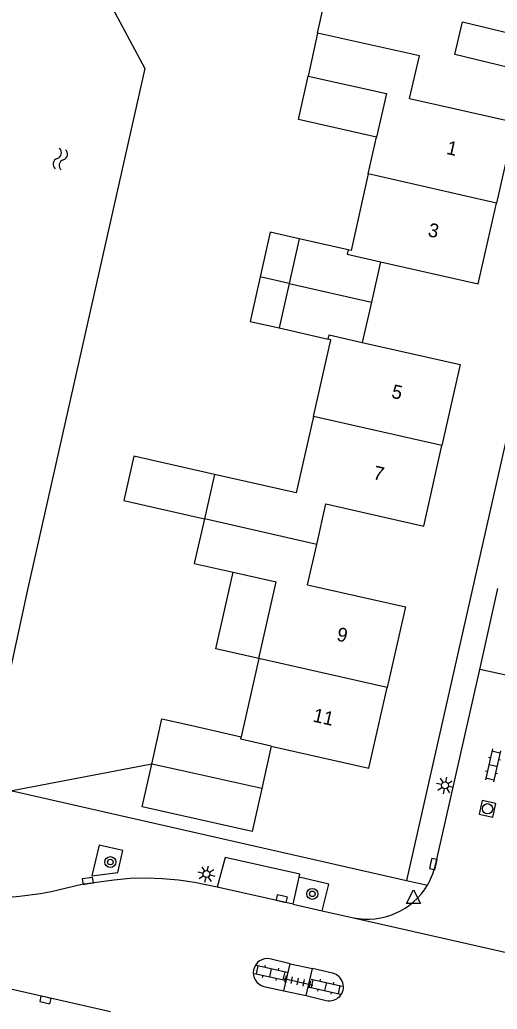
# Model space of a CAD drawing. Extents: x 128000 to 131008, y 398996 to 402500.
# Drawn here: x 128852.8 to 128887.5, y 399302.4 to 399374.1 of the extents above; entities that cross this region are included whole.
import ezdxf

# ---------------------------------------------------------------- set-up
doc = ezdxf.new("R2010")
doc.units = 0
for name, color, linetype in [('gg-afsc-erfafscheiding', 7, 'Continuous'), ('gg-anno-huisnummerreeks BGT', 7, 'Continuous'), ('gg-bbg-bijgebouw', 7, 'Continuous'), ('gg-bbg-gedigitaliseerde bebouwing', 7, 'Continuous'), ('gg-bbg-gedigitaliseerde bijgebouw', 7, 'Continuous'), ('gg-bbg-hoofdgebouw', 7, 'Continuous'), ('gg-bbg-luifel en loopbrug', 7, 'Continuous'), ('gg-bbg-tussenscheiding', 7, 'Continuous'), ('gg-knt-verharding', 7, 'Continuous'), ('gg-knt-verharding nz', 7, 'Continuous'), ('gg-kntw-beschoeiing', 7, 'Continuous'), ('gt-grn-vlakafsluiter', 7, 'Continuous'), ('gt-grn-weggrens', 7, 'Continuous'), ('gt-symb-boom', 7, 'Continuous'), ('gt-symb-klinker verharding', 7, 'Continuous'), ('gt-symb-kolk', 7, 'Continuous'), ('gt-symb-lichtmast', 7, 'Continuous'), ('gt-symb-rioolschacht', 7, 'Continuous'), ('gt-symb-tegel verharding', 7, 'Continuous'), ('gt-symb-waterafsluiter', 7, 'Continuous'), ('gt-symb-watersymbool', 7, 'Continuous')]:
    doc.layers.add(name, color=color, linetype=linetype)

# ---------------------------------------------------------------- blocks, each defined once
blk = doc.blocks.new('gt0-WA')
at = {"layer": 'gt-symb-watersymbool'}
for centre, start, end in [((-0.323, 0.022), 28.07249, 151.92751), ((0.427, 0.422), 208.07248, 331.92751), ((-0.323, -0.428), 28.07249, 151.92751), ((0.427, -0.028), 208.07248, 331.92751)]:
    blk.add_arc(centre, 0.425, start, end, dxfattribs=at)
blk = doc.blocks.new('gt0-WAFSL')
at = {"layer": 'gt-symb-waterafsluiter'}
for p, q in [((-0.5, -0.333), (0, 0.667)), ((0, 0.667), (0.5, -0.333)), ((0.5, -0.333), (-0.5, -0.333))]:
    blk.add_line(p, q, dxfattribs=at)
blk = doc.blocks.new('gt0-KOLK')
at = {"layer": 'gt-symb-kolk'}
blk.add_lwpolyline([(0, 0), (0.375, 0), (0.375, 0.4), (-0.375, 0.4), (-0.375, 0), (0, 0)], dxfattribs=at)
blk = doc.blocks.new('gt0-LMAST')
at = {"layer": 'gt-symb-lichtmast'}
for p, q in [((-0.182, 0.173), (-0.447, 0.438)), ((-0.005, 0.246), (-0.005, 0.621)), ((0.172, 0.173), (0.437, 0.438)), ((-0.255, -0.004), (-0.63, -0.004)), ((-0.182, -0.181), (-0.447, -0.446)), ((-0.005, -0.254), (-0.005, -0.629)), ((0.437, -0.446), (0.172, -0.181)), ((0.245, -0.004), (0.62, -0.004))]:
    blk.add_line(p, q, dxfattribs=at)
blk.add_circle((-0.005, -0.004), 0.25, dxfattribs=at)
blk = doc.blocks.new('gt0-RS')
at = {"layer": 'gt-symb-rioolschacht'}
blk.add_lwpolyline([(-0.5, -0.5), (0.5, -0.5), (0.5, 0.5), (-0.5, 0.5)], close=True, dxfattribs=at)
blk.add_circle((0, 0), 0.375, dxfattribs=at)
blk = doc.blocks.new('gt0-KL1')
at = {"layer": 'gt-symb-klinker verharding'}
for p, q in [((-1.15, 0.3), (1.15, 0.3)), ((-1, -0.3), (-1, 0.3)), ((-0.5, 0.3), (-0.5, 0.45)), ((0, -0.3), (0, 0.3)), ((0.5, 0.3), (0.5, 0.45)), ((1, -0.3), (1, 0.3)), ((-1.15, -0.3), (1.15, -0.3)), ((-0.5, -0.45), (-0.5, -0.3)), ((0.5, -0.45), (0.5, -0.3))]:
    blk.add_line(p, q, dxfattribs=at)
blk = doc.blocks.new('gt0-TEG1')
at = {"layer": 'gt-symb-tegel verharding'}
for p, q in [((-1.125, 0), (1.125, 0)), ((-0.9, -0.25), (-0.9, 0.25)), ((-0.45, -0.25), (-0.45, 0.25)), ((0, -0.25), (0, 0.25)), ((0.45, -0.25), (0.45, 0.25)), ((0.9, -0.25), (0.9, 0.25))]:
    blk.add_line(p, q, dxfattribs=at)
blk = doc.blocks.new('gt0-BOOM')
at = {"layer": 'gt-symb-boom'}
for radius in [0.4, 0.2]:
    blk.add_circle((0, 0), radius, dxfattribs=at)

msp = doc.modelspace()

# ---------------------------------------------------------------- linework, layer by layer
at = {"layer": 'gg-afsc-erfafscheiding'}
msp.add_line((128852.286, 399318.268), (128880.893, 399311.77), dxfattribs=at)
at = {"layer": 'gg-bbg-bijgebouw'}
msp.add_line((128871.087, 399321.504), (128870.397, 399318.43), dxfattribs=at)
for points in [[(128890.471, 399372.678), (128889.905, 399370.311), (128884.406, 399371.629), (128884.972, 399373.996), (128890.471, 399372.678)], [(128862.42, 399320.21), (128863.14, 399323.48), (128865.24, 399323.02), (128868.915, 399322.189)], [(128870.397, 399318.43), (128864.52, 399319.75), (128862.42, 399320.21)]]:
    msp.add_lwpolyline(points, dxfattribs=at)
at = {"layer": 'gg-bbg-gedigitaliseerde bebouwing'}
for p, q in [((128874.449, 399373.171), (128873.764, 399370.065)), ((128873.764, 399370.065), (128879.45, 399368.812)), ((128879.45, 399368.812), (128878.731, 399365.631)), ((128866.967, 399341.203), (128866.236, 399337.974)), ((128872.907, 399339.86), (128866.967, 399341.203)), ((128868.33, 399334.108), (128871.451, 399333.402))]:
    msp.add_line(p, q, dxfattribs=at)
msp.add_lwpolyline([(128866.236, 399337.974), (128865.506, 399334.747), (128868.33, 399334.108)], dxfattribs=at)
at = {"layer": 'gg-bbg-gedigitaliseerde bijgebouw'}
for p, q in [((128873.111, 399358.269), (128872.38, 399355.04)), ((128872.38, 399355.04), (128871.65, 399351.812))]:
    msp.add_line(p, q, dxfattribs=at)
for points in [[(128873.111, 399358.269), (128871.014, 399358.743), (128870.283, 399355.515)], [(128870.283, 399355.515), (128869.553, 399352.287), (128871.65, 399351.812)]]:
    msp.add_lwpolyline(points, dxfattribs=at)
at = {"layer": 'gg-bbg-hoofdgebouw'}
for p, q in [((128878.13, 399362.971), (128878.731, 399365.631)), ((128878.13, 399362.971), (128876.875, 399357.417)), ((128876.875, 399357.417), (128876.671, 399357.463)), ((128874.16, 399345.404), (128872.907, 399339.86)), ((128874.392, 399336.129), (128875.058, 399339.055)), ((128873.726, 399333.204), (128874.392, 399336.129)), ((128870.195, 399327.851), (128871.451, 399333.402)), ((128870.195, 399327.851), (128868.915, 399322.189))]:
    msp.add_line(p, q, dxfattribs=at)
for points in [[(128881.123, 399368.443), (128881.839, 399371.542), (128874.449, 399373.171)], [(128881.123, 399368.443), (128888.76, 399366.72), (128887.435, 399360.865)], [(128879.018, 399356.615), (128886.11, 399355.01), (128887.435, 399360.865)], [(128876.671, 399357.463), (128876.603, 399357.161), (128879.018, 399356.615)], [(128875.211, 399351.006), (128875.28, 399351.309), (128877.694, 399350.764)], [(128874.16, 399345.404), (128875.415, 399350.96), (128875.211, 399351.006)], [(128877.694, 399350.764), (128884.79, 399349.16), (128883.47, 399343.305)], [(128875.058, 399339.055), (128882.15, 399337.45), (128883.47, 399343.305)], [(128873.726, 399333.204), (128880.82, 399331.6), (128879.5, 399325.75)], [(128871.087, 399321.504), (128878.18, 399319.9), (128879.5, 399325.75)]]:
    msp.add_lwpolyline(points, dxfattribs=at)
at = {"layer": 'gg-bbg-luifel en loopbrug'}
for p, q in [((128876.671, 399357.463), (128873.111, 399358.269)), ((128879.018, 399356.615), (128878.356, 399353.689)), ((128872.38, 399355.04), (128878.356, 399353.689)), ((128878.356, 399353.689), (128877.694, 399350.764)), ((128871.65, 399351.812), (128875.211, 399351.006))]:
    msp.add_line(p, q, dxfattribs=at)
for points in [[(128878.731, 399365.631), (128873.053, 399366.914), (128873.764, 399370.065)], [(128866.967, 399341.203), (128861.115, 399342.526), (128860.385, 399339.297), (128866.236, 399337.974)], [(128870.195, 399327.851), (128867.074, 399328.557), (128868.33, 399334.108)], [(128870.397, 399318.43), (128869.691, 399315.309), (128861.719, 399317.111), (128862.42, 399320.21)]]:
    msp.add_lwpolyline(points, dxfattribs=at)
at = {"layer": 'gg-bbg-tussenscheiding'}
for p, q in [((128887.435, 399360.865), (128878.13, 399362.971)), ((128872.38, 399355.04), (128870.283, 399355.515)), ((128883.47, 399343.305), (128874.16, 399345.404)), ((128874.392, 399336.129), (128866.236, 399337.974)), ((128879.5, 399325.75), (128870.195, 399327.851))]:
    msp.add_line(p, q, dxfattribs=at)
msp.add_lwpolyline([(128871.087, 399321.504), (128868.873, 399322.005), (128868.915, 399322.189)], dxfattribs=at)
at = {"layer": 'gg-knt-verharding'}
for p, q in [((128894.666, 399372.637), (128880.893, 399311.77)), ((128886.212, 399327.072), (128887.535, 399332.936)), ((128891.095, 399325.977), (128886.212, 399327.072)), ((128859.413, 399302.246), (128808.153, 399313.868)), ((128872.671, 399310.054), (128873.113, 399312.014)), ((128872.671, 399310.054), (128874.782, 399309.579)), ((128874.782, 399309.579), (128877.051, 399309.069)), ((128872.46, 399305.74), (128870.99, 399306.09)), ((128872.01, 399303.77), (128872.46, 399305.74)), ((128872.46, 399305.74), (128874.07, 399305.38)), ((128873.62, 399303.43), (128874.07, 399305.38)), ((128875.542, 399305.045), (128874.07, 399305.38)), ((128870.548, 399304.098), (128872.01, 399303.77)), ((128872.01, 399303.77), (128873.62, 399303.43)), ((128873.62, 399303.43), (128875.083, 399303.079))]:
    msp.add_line(p, q, dxfattribs=at)
for points in [[(128882.548, 399311.653), (128882.819, 399312.251), (128883.01, 399312.88), (128886.212, 399327.072)], [(128859.954, 399312.351), (128860.313, 399313.946), (128858.589, 399314.33), (128858.064, 399312.1), (128859.954, 399312.351)], [(128873.113, 399312.014), (128873.16, 399312.225), (128867.749, 399313.442), (128867.161, 399311.292)], [(128867.161, 399311.292), (128865.527, 399311.629), (128864.363, 399311.796), (128863.192, 399311.9), (128862.017, 399311.94), (128860.842, 399311.91), (128859.672, 399311.802), (128857.346, 399311.469), (128855.106, 399310.94), (128854.351, 399310.799), (128852.828, 399310.601), (128852.062, 399310.545), (128851.293, 399310.543), (128847.695, 399310.745), (128845.837, 399311.165)], [(128874.782, 399309.579), (128875.259, 399311.51), (128873.113, 399312.014)]]:
    msp.add_lwpolyline(points, dxfattribs=at)
for centre, radius, start, end in [((128877.497, 399314.351), 5.726, 329.34299, 331.8925), ((128878.072, 399314.037), 5.072, 258.39063, 329.07833), ((128870.808, 399305.085), 1.021, 79.71222, 255.26671), ((128875.317, 399304.061), 1.009, 256.59114, 77.12608)]:
    msp.add_arc(centre, radius, start, end, dxfattribs=at)
at = {"layer": 'gg-knt-verharding nz'}
msp.add_line((128872.671, 399310.054), (128867.161, 399311.292), dxfattribs=at)
at = {"layer": 'gg-kntw-beschoeiing'}
msp.add_lwpolyline([(128861.7, 399398.17), (128863.66, 399395.08), (128859.381, 399375.341), (128861.926, 399370.612), (128853.42, 399332.96), (128852.11, 399326.91), (128849.09, 399325.03)], dxfattribs=at)
at = {"layer": 'gt-grn-vlakafsluiter'}
for p, q in [((128874.449, 399373.171), (128875.29, 399376.901)), ((128862.42, 399320.21), (128852.286, 399318.268))]:
    msp.add_line(p, q, dxfattribs=at)
at = {"layer": 'gt-grn-weggrens'}
for p, q in [((128880.893, 399311.77), (128882.423, 399311.431)), ((128877.051, 399309.069), (128891.568, 399305.779))]:
    msp.add_line(p, q, dxfattribs=at)

# ---------------------------------------------------------------- block references
at = {"layer": 'gt-symb-boom'}
for p in [(128859.415, 399313.103), (128874.073, 399310.801)]:
    msp.add_blockref('gt0-BOOM', p, dxfattribs=at)
at = {"layer": 'gt-symb-klinker verharding'}
for p, rotation in [((128887.171, 399320.113), -102.64685349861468), ((128871.051, 399305.08), -12.702731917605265), ((128875.047, 399304.079), -12.702731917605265)]:
    msp.add_blockref('gt0-KL1', p, dxfattribs=dict(at, rotation=rotation))
at = {"layer": 'gt-symb-kolk'}
for p, rotation in [((128882.645, 399313.007), -102.71533698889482), ((128857.808, 399311.54), 8.802804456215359), ((128871.89, 399310.649), 167.22875743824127), ((128854.745, 399303.305), 167.22875743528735)]:
    msp.add_blockref('gt0-KOLK', p, dxfattribs=dict(at, rotation=rotation))
at = {"layer": 'gt-symb-lichtmast'}
for p, rotation in [((128883.697, 399318.654), -102.71533698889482), ((128866.38, 399312.23), 167.22875743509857)]:
    msp.add_blockref('gt0-LMAST', p, dxfattribs=dict(at, rotation=rotation))
at = {"layer": 'gt-symb-rioolschacht', "rotation": -102.70273191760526}
msp.add_blockref('gt0-RS', (128886.781, 399316.965), dxfattribs=at)
at = {"layer": 'gt-symb-tegel verharding', "rotation": -12.758585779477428}
msp.add_blockref('gt0-TEG1', (128873.018, 399304.443), dxfattribs=at)
at = {"layer": 'gt-symb-waterafsluiter'}
msp.add_blockref('gt0-WAFSL', (128881.411, 399310.429), dxfattribs=at)
at = {"layer": 'gt-symb-watersymbool', "rotation": 78.52151796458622}
msp.add_blockref('gt0-WA', (128855.765, 399363.991), dxfattribs=at)

# ---------------------------------------------------------------- texts
at = {"layer": 'gg-anno-huisnummerreeks BGT'}
for s, rotation, p in [('1', 347.2, (128883.743, 399364.434)), ('3', 347.2, (128882.394, 399358.476)), ('5', 347.3, (128879.752, 399346.767)), ('7', 347.3, (128878.423, 399340.872)), ('9', 347.3, (128875.774, 399329.174)), ('11', 347.3, (128874.05, 399323.297))]:
    msp.add_text(s, height=1, rotation=rotation, dxfattribs=at).set_placement(p)

doc.saveas('drawing.dxf')
